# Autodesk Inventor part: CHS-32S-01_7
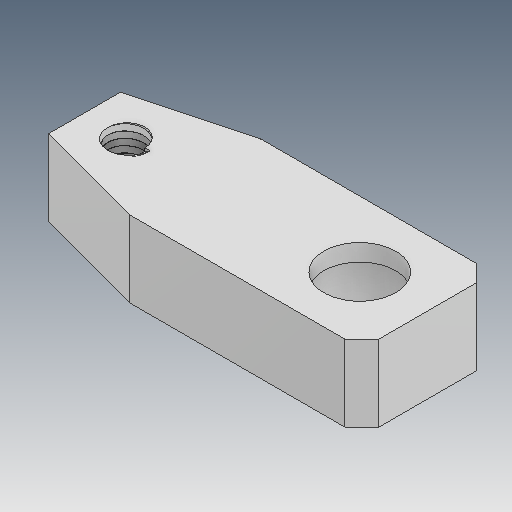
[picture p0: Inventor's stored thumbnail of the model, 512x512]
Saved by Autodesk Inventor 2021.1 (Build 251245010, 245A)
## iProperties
Created: 2021-05
Part Number: CHS-32S-01_7
Material: Ogólny
Document SubType Name: Modeling
Designer: user
Density: 1 g/cm^3
Appearance: Domyślna
Author: user
Revision Number: ÈÎºÎ
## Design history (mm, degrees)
feature "ÊäÈë1"
node "Bryła1"
